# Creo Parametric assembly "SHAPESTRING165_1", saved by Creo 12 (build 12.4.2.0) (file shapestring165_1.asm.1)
Units: Custom; MM, KILOGRAM, SECS

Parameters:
  PTC_WM_ITERATION = "0"
  PTC_WM_VERSION = "-.0"
  PTC_WM_LIFECYCLE_STATE = "In Work"
  PTC_WM_LIFECYCLE = "MO_CADDocument"
  PTC_WM_CREATED_BY = "Maximilian Roepper (Z0017RMS: MO)"
  PTC_WM_CREATED_ON = "18-Sep-26 11:36:42 AM"
  PTC_WM_MODIFIED_BY = "Maximilian Roepper (Z0017RMS: MO)"
  PTC_WM_MODIFIED_ON = "18-Sep-26 11:36:46 AM"
  PDMLINKNUMBER = "PDM000071455166"
  PTC_WM_NAME = "shapestring165_1.asm"
  PTC_WM_NUMBER = "PDM000071455166"

Other parameters: WEIGHT, WEIGHT_FACTOR, WEIGHT_ADD, MC_ERRORS, SUPPLIER, ISPOSITIONINGASSEMBLY

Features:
  1. coordinate system
  2. imported feature
  3. component "SHAPESTRING079_1"
  4. component "SHAPESTRING164_1"

Other named items: DRW_VIEW_ORG, ROUGH-GROB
